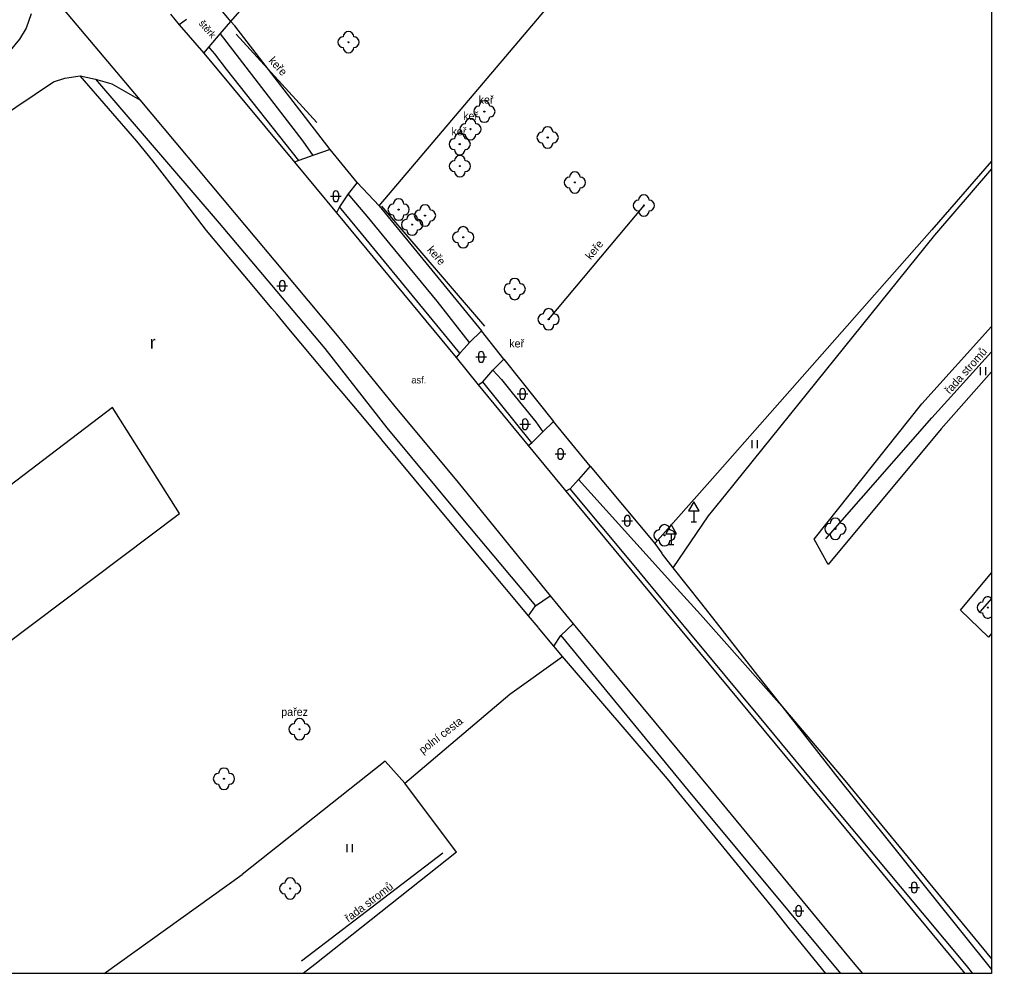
# Model space of a CAD drawing. Extents: x -594386 to -594050, y -1167541 to -1167175.
# Drawn here: x -594140.8 to -594049.8, y -1167540.8 to -1167451.4 of the extents above; entities that cross this region are included whole.
import ezdxf

# ---------------------------------------------------------------- set-up
doc = ezdxf.new("R2010")
doc.units = 0
for name, color, linetype in [('Level 14', 7, 'Continuous'), ('Level 22', 7, 'Continuous'), ('Level 34', 7, 'Continuous'), ('Level 36', 7, 'Continuous'), ('Level 41', 7, 'Continuous'), ('Vrstva 10', 7, 'Continuous'), ('Vrstva 11', 7, 'Continuous'), ('Vrstva 40', 7, 'Continuous'), ('Vrstva 42', 7, 'Continuous'), ('Vrstva 63', 7, 'Continuous'), ('Vrstva 7', 7, 'Continuous'), ('Vrstva 8', 7, 'Continuous')]:
    doc.layers.add(name, color=color, linetype=linetype)

msp = doc.modelspace()

# ---------------------------------------------------------------- linework, layer by layer
at = {"layer": 'Level 14'}
for points in [[(-594122.02, -1167452.75), (-594114.26, -1167462.8), (-594113.33, -1167464.15)], [(-594098.65, -1167481.66), (-594101.68, -1167477.78), (-594105.64, -1167472.99), (-594108.24, -1167469.82), (-594110.01, -1167467.73)], [(-594096.46, -1167484.27), (-594095.64, -1167485.14), (-594094.64, -1167486.38), (-594092.43, -1167489.11), (-594091.79, -1167490.03)]]:
    msp.add_lwpolyline(points, dxfattribs=at)
at = {"layer": 'Level 22'}
for centre in [(-594109.99, -1167453.53), (-594097.26, -1167460.03), (-594098.56, -1167461.68), (-594091.33, -1167462.46), (-594099.57, -1167463.08), (-594099.55, -1167465.14), (-594088.78, -1167466.67), (-594105.29, -1167469.21), (-594082.32, -1167468.83), (-594102.82, -1167469.77), (-594104.03, -1167470.62), (-594099.24, -1167471.81), (-594094.42, -1167476.66), (-594091.24, -1167479.49), (-594064.38, -1167499.12), (-594080.38, -1167499.73), (-594050.1, -1167506.5), (-594114.58, -1167517.9), (-594121.65, -1167522.54), (-594115.45, -1167532.82)]:
    msp.add_circle(centre, 0.05, dxfattribs=at)
for centre, start, end in [((-594109.99, -1167453.03), 0, 180), ((-594110.49, -1167453.53), 90, 270), ((-594109.49, -1167453.53), 270, 90), ((-594109.99, -1167454.03), 180, 0), ((-594097.26, -1167459.53), 0, 180), ((-594097.76, -1167460.03), 90, 270), ((-594096.76, -1167460.03), 270, 90), ((-594098.56, -1167461.18), 0, 180), ((-594097.26, -1167460.53), 180, 0), ((-594099.06, -1167461.68), 90, 270), ((-594098.06, -1167461.68), 270, 90), ((-594091.83, -1167462.46), 90, 270), ((-594091.33, -1167461.96), 0, 180), ((-594090.83, -1167462.46), 270, 90), ((-594100.07, -1167463.08), 90, 270), ((-594099.57, -1167462.58), 0, 180), ((-594099.07, -1167463.08), 270, 90), ((-594098.56, -1167462.18), 180, 0), ((-594099.57, -1167463.58), 180, 0), ((-594091.33, -1167462.96), 180, 0), ((-594100.05, -1167465.14), 90, 270), ((-594099.55, -1167464.64), 0, 180), ((-594099.05, -1167465.14), 270, 90), ((-594099.55, -1167465.64), 180, 0), ((-594088.78, -1167466.17), 0, 180), ((-594089.28, -1167466.67), 90, 270), ((-594088.28, -1167466.67), 270, 90), ((-594088.78, -1167467.17), 180, 0), ((-594105.29, -1167468.71), 0, 180), ((-594082.82, -1167468.83), 90, 270), ((-594082.32, -1167468.33), 0, 180), ((-594081.82, -1167468.83), 270, 90), ((-594105.79, -1167469.21), 90, 270), ((-594104.79, -1167469.21), 270, 90), ((-594103.32, -1167469.77), 90, 270), ((-594102.82, -1167469.27), 0, 180), ((-594102.32, -1167469.77), 270, 90), ((-594082.32, -1167469.33), 180, 0), ((-594105.29, -1167469.71), 180, 0), ((-594104.53, -1167470.62), 90, 270), ((-594104.03, -1167470.12), 0, 180), ((-594103.53, -1167470.62), 270, 90), ((-594104.03, -1167471.12), 180, 0), ((-594102.82, -1167470.27), 180, 0), ((-594099.24, -1167471.31), 0, 180), ((-594099.74, -1167471.81), 90, 270), ((-594098.74, -1167471.81), 270, 90), ((-594099.24, -1167472.31), 180, 0), ((-594094.42, -1167476.16), 0, 180), ((-594094.92, -1167476.66), 90, 270), ((-594093.92, -1167476.66), 270, 90), ((-594094.42, -1167477.16), 180, 0), ((-594091.74, -1167479.49), 90, 270), ((-594091.24, -1167478.99), 0, 180), ((-594090.74, -1167479.49), 270, 90), ((-594091.24, -1167479.99), 180, 0), ((-594064.38, -1167498.62), 0, 180), ((-594080.88, -1167499.73), 90, 270), ((-594080.38, -1167499.23), 0, 180), ((-594079.88, -1167499.73), 270, 90), ((-594064.88, -1167499.12), 90, 270), ((-594063.88, -1167499.12), 270, 90), ((-594080.38, -1167500.23), 180, 0), ((-594064.38, -1167499.62), 180, 0), ((-594050.1, -1167506), 45.573, 180), ((-594050.6, -1167506.5), 90, 270), ((-594050.1, -1167507), 180, 314.427), ((-594115.08, -1167517.9), 90, 270), ((-594114.58, -1167517.4), 0, 180), ((-594114.08, -1167517.9), 270, 90), ((-594114.58, -1167518.4), 180, 0), ((-594122.15, -1167522.54), 90, 270), ((-594121.65, -1167522.04), 0, 180), ((-594121.15, -1167522.54), 270, 90), ((-594121.65, -1167523.04), 180, 0), ((-594115.45, -1167532.32), 0, 180), ((-594115.95, -1167532.82), 90, 270), ((-594114.95, -1167532.82), 270, 90), ((-594115.45, -1167533.32), 180, 0)]:
    msp.add_arc(centre, 0.5, start, end, dxfattribs=at)
at = {"layer": 'Level 34'}
for p, q in [((-594077.64, -1167497.452), (-594077.64, -1167498.47)), ((-594077.89, -1167498.47), (-594077.39, -1167498.47)), ((-594079.77, -1167499.582), (-594079.77, -1167500.6)), ((-594080.02, -1167500.6), (-594079.52, -1167500.6))]:
    msp.add_line(p, q, dxfattribs=at)
for points in [[(-594078.14, -1167497.452), (-594077.14, -1167497.452), (-594077.64, -1167496.586)], [(-594080.27, -1167499.582), (-594079.27, -1167499.582), (-594079.77, -1167498.716)]]:
    msp.add_lwpolyline(points, close=True, dxfattribs=at)
at = {"layer": 'Level 36'}
for p, q in [((-594111.676, -1167467.966), (-594110.676, -1167467.966)), ((-594111.426, -1167467.716), (-594111.426, -1167468.216)), ((-594110.926, -1167467.716), (-594110.926, -1167468.216)), ((-594116.686, -1167476.356), (-594115.686, -1167476.356)), ((-594116.436, -1167476.106), (-594116.436, -1167476.606)), ((-594115.936, -1167476.106), (-594115.936, -1167476.606)), ((-594097.806, -1167482.766), (-594097.806, -1167483.266)), ((-594097.306, -1167482.766), (-594097.306, -1167483.266)), ((-594098.056, -1167483.016), (-594097.056, -1167483.016)), ((-594050.784, -1167484.723), (-594050.784, -1167483.973)), ((-594050.284, -1167484.723), (-594050.284, -1167483.973)), ((-594094.186, -1167486.486), (-594093.186, -1167486.486)), ((-594093.936, -1167486.236), (-594093.936, -1167486.736)), ((-594093.436, -1167486.236), (-594093.436, -1167486.736)), ((-594093.946, -1167489.326), (-594092.946, -1167489.326)), ((-594093.696, -1167489.076), (-594093.696, -1167489.576)), ((-594093.196, -1167489.076), (-594093.196, -1167489.576)), ((-594072.164, -1167491.553), (-594072.164, -1167490.803)), ((-594071.664, -1167491.553), (-594071.664, -1167490.803)), ((-594090.386, -1167491.856), (-594090.386, -1167492.356)), ((-594089.886, -1167491.856), (-594089.886, -1167492.356)), ((-594090.636, -1167492.106), (-594089.636, -1167492.106)), ((-594084.376, -1167498.366), (-594083.376, -1167498.366)), ((-594084.126, -1167498.116), (-594084.126, -1167498.616)), ((-594083.626, -1167498.116), (-594083.626, -1167498.616)), ((-594110.104, -1167529.423), (-594110.104, -1167528.673)), ((-594109.604, -1167529.423), (-594109.604, -1167528.673)), ((-594057.496, -1167532.726), (-594056.496, -1167532.726)), ((-594057.246, -1167532.476), (-594057.246, -1167532.976)), ((-594056.746, -1167532.476), (-594056.746, -1167532.976)), ((-594068.076, -1167534.676), (-594068.076, -1167535.176)), ((-594067.576, -1167534.676), (-594067.576, -1167535.176)), ((-594068.326, -1167534.926), (-594067.326, -1167534.926))]:
    msp.add_line(p, q, dxfattribs=at)
for centre, start, end in [((-594111.176, -1167467.716), 0, 180), ((-594111.176, -1167468.216), 180, 0), ((-594116.186, -1167476.106), 0, 180), ((-594116.186, -1167476.606), 180, 0), ((-594097.556, -1167482.766), 0, 180), ((-594097.556, -1167483.266), 180, 0), ((-594093.686, -1167486.236), 0, 180), ((-594093.686, -1167486.736), 180, 0), ((-594093.446, -1167489.076), 0, 180), ((-594093.446, -1167489.576), 180, 0), ((-594090.136, -1167491.856), 0, 180), ((-594090.136, -1167492.356), 180, 0), ((-594083.876, -1167498.116), 0, 180), ((-594083.876, -1167498.616), 180, 0), ((-594056.996, -1167532.476), 0, 180), ((-594056.996, -1167532.976), 180, 0), ((-594067.826, -1167534.676), 0, 180), ((-594067.826, -1167535.176), 180, 0)]:
    msp.add_arc(centre, 0.25, start, end, dxfattribs=at)
at = {"layer": 'Vrstva 10'}
for points in [[(-594140.14, -1167446.31), (-594129.52, -1167458.94)], [(-594139.7, -1167450.87), (-594140.18, -1167452.21), (-594140.81, -1167453.25), (-594141.67, -1167454.31), (-594142.79, -1167455.28), (-594143.9, -1167456.06)], [(-594126.67, -1167450.89), (-594125.84, -1167451.9)], [(-594125.84, -1167451.9), (-594123.54, -1167454.55)], [(-594123.54, -1167454.55), (-594115.06, -1167464.78)], [(-594142.9, -1167460.77), (-594137.62, -1167457.25), (-594136.57, -1167456.9), (-594135.11, -1167456.68)], [(-594135.11, -1167456.68), (-594133.67, -1167456.99)], [(-594133.67, -1167456.99), (-594132.15, -1167457.42), (-594129.52, -1167458.94)], [(-594129.52, -1167458.94), (-594120.69, -1167469.47), (-594115.06, -1167476.23)], [(-594115.06, -1167464.78), (-594111.12, -1167469.53)], [(-594111.12, -1167469.53), (-594099.9, -1167483.08)], [(-594115.06, -1167476.23), (-594111.04, -1167481.01), (-594105.76, -1167487.49)], [(-594099.9, -1167483.08), (-594097.84, -1167485.63)], [(-594097.84, -1167485.63), (-594093.16, -1167491.33)], [(-594105.76, -1167487.49), (-594099.7, -1167494.77), (-594091.09, -1167505.4)], [(-594093.16, -1167491.33), (-594089.63, -1167495.58)], [(-594089.63, -1167495.58), (-594065.5, -1167524.72), (-594052.244, -1167540.79)], [(-594091.09, -1167505.4), (-594088.93, -1167508.03)], [(-594088.93, -1167508.03), (-594076.06, -1167523.59), (-594062.72, -1167539.74), (-594061.849, -1167540.79)]]:
    msp.add_lwpolyline(points, dxfattribs=at)
at = {"layer": 'Vrstva 11'}
for p, q in [((-594049.75, -1167465.402), (-594055.1, -1167471.61)), ((-594049.75, -1167508.942), (-594050.03, -1167509.27)), ((-594132.872, -1167540.79), (-594119.96, -1167531.52))]:
    msp.add_line(p, q, dxfattribs=at)
for points in [[(-594121, -1167451.58), (-594079.89, -1167404.5), (-594071.72, -1167395.67)], [(-594125.15, -1167451.39), (-594125.84, -1167451.9)], [(-594122.02, -1167452.75), (-594121, -1167451.58)], [(-594123.05, -1167453.97), (-594122.02, -1167452.75)], [(-594123.54, -1167454.55), (-594123.05, -1167453.97)], [(-594114.63, -1167464.6), (-594121.41, -1167456.05), (-594122.52, -1167454.61), (-594122.93, -1167454.11), (-594123.05, -1167453.97)], [(-594117.16, -1167478.48), (-594118.85, -1167476.46), (-594121.51, -1167473.3), (-594121.83, -1167472.92), (-594123.29, -1167471.16), (-594125.23, -1167468.64), (-594125.61, -1167468.14), (-594128.33, -1167464.65), (-594129.81, -1167462.79), (-594135.11, -1167456.68)], [(-594133.67, -1167456.99), (-594122.09, -1167470.48), (-594117.2, -1167476.29)], [(-594111.7, -1167463.59), (-594113.33, -1167464.15)], [(-594114.63, -1167464.6), (-594115.06, -1167464.78)], [(-594113.33, -1167464.15), (-594114.63, -1167464.6)], [(-594109.16, -1167466.66), (-594110.01, -1167467.73)], [(-594110.01, -1167467.73), (-594110.82, -1167468.94)], [(-594110.82, -1167468.94), (-594111.12, -1167469.53)], [(-594099.55, -1167482.68), (-594108.78, -1167471.45), (-594110.82, -1167468.94)], [(-594055.1, -1167471.61), (-594074.667, -1167495.894)], [(-594117.2, -1167476.29), (-594112.21, -1167482.22), (-594106.4, -1167489.65)], [(-594106.87, -1167490.77), (-594106.94, -1167490.69), (-594109, -1167488.22), (-594110.49, -1167486.45), (-594111.07, -1167485.75), (-594115.56, -1167480.39), (-594116.71, -1167479.01), (-594117.16, -1167478.48)], [(-594049.75, -1167484.427), (-594054.46, -1167489.75), (-594065.04, -1167502.45), (-594066.37, -1167500.1), (-594056.27, -1167487.42), (-594049.75, -1167480.154)], [(-594097.52, -1167480.56), (-594098.65, -1167481.66)], [(-594098.65, -1167481.66), (-594099.15, -1167482.23), (-594099.55, -1167482.68)], [(-594099.55, -1167482.68), (-594099.9, -1167483.08)], [(-594096.46, -1167484.27), (-594095.45, -1167483.24)], [(-594097.41, -1167485.36), (-594096.46, -1167484.27)], [(-594097.84, -1167485.63), (-594097.41, -1167485.36)], [(-594092.8, -1167491.05), (-594097.41, -1167485.36)], [(-594183.067, -1167540.79), (-594125.813, -1167497.688), (-594132.097, -1167487.766), (-594201.7, -1167540.79)], [(-594091.79, -1167490.03), (-594090.78, -1167489.07)], [(-594106.4, -1167489.65), (-594099.47, -1167498.01), (-594092.48, -1167506.35)], [(-594092.8, -1167491.05), (-594091.79, -1167490.03)], [(-594093.12, -1167507.26), (-594097.39, -1167502.16), (-594100.73, -1167498.16), (-594106.87, -1167490.77)], [(-594093.16, -1167491.33), (-594092.8, -1167491.05)], [(-594087.34, -1167493.24), (-594088.45, -1167494.5)], [(-594088.45, -1167494.5), (-594089.23, -1167495.39)], [(-594088.45, -1167494.5), (-594079.51, -1167504.39)], [(-594089.23, -1167495.39), (-594089.63, -1167495.58)], [(-594051.49, -1167540.79), (-594052.1, -1167540.04), (-594064.45, -1167525.24), (-594071.5, -1167516.73), (-594078.09, -1167508.81), (-594083.22, -1167502.57), (-594089.23, -1167495.39)], [(-594074.667, -1167495.894), (-594076.3, -1167497.92)], [(-594076.3, -1167497.92), (-594079.59, -1167502.77)], [(-594081.29, -1167500.51), (-594080.65, -1167501.41), (-594080.59, -1167501.49), (-594079.59, -1167502.77)], [(-594079.59, -1167502.77), (-594076.93, -1167506.16), (-594074.99, -1167508.63), (-594071.68, -1167512.85), (-594069.41, -1167515.74)], [(-594050.03, -1167509.27), (-594052.67, -1167506.74), (-594049.75, -1167503.237)], [(-594079.51, -1167504.39), (-594077.02, -1167507.16), (-594069.41, -1167515.74)], [(-594092.48, -1167506.35), (-594091.09, -1167505.4)], [(-594093.12, -1167507.26), (-594092.48, -1167506.35)], [(-594092.18, -1167508.4), (-594092.23, -1167508.33), (-594093.12, -1167507.26)], [(-594090.76, -1167510.11), (-594092.18, -1167508.4)], [(-594090.11, -1167509.11), (-594088.93, -1167508.03)], [(-594090.76, -1167510.11), (-594090.11, -1167509.11)], [(-594090.11, -1167509.11), (-594078.16, -1167523.65), (-594063.893, -1167540.79)], [(-594089.931, -1167511.078), (-594090.76, -1167510.11)], [(-594104.72, -1167522.96), (-594094.86, -1167514.62), (-594089.931, -1167511.078)], [(-594065.27, -1167540.79), (-594068.67, -1167536.59), (-594070.09, -1167534.82), (-594074.81, -1167529.04), (-594079.32, -1167523.5), (-594079.83, -1167522.88), (-594080.1, -1167522.55), (-594089.931, -1167511.078)], [(-594069.41, -1167515.74), (-594063.48, -1167522.69), (-594049.75, -1167539.411)], [(-594069.41, -1167515.74), (-594065.37, -1167520.89), (-594064.02, -1167522.61), (-594059.56, -1167528.17), (-594055.43, -1167533.33), (-594049.75, -1167540.418)], [(-594106.56, -1167520.88), (-594119.96, -1167531.52)], [(-594106.56, -1167520.88), (-594104.72, -1167522.96)], [(-594099.86, -1167529.43), (-594104.72, -1167522.96)], [(-594099.86, -1167529.43), (-594113.15, -1167539.94), (-594114.244, -1167540.79)]]:
    msp.add_lwpolyline(points, dxfattribs=at)
at = {"layer": 'Vrstva 63'}
msp.add_lwpolyline([(-594386.36, -1167175.43), (-594049.75, -1167175.43), (-594049.75, -1167540.79), (-594386.36, -1167540.79)], close=True, dxfattribs=at)
at = {"layer": 'Vrstva 7'}
msp.add_line((-594049.75, -1167505.643), (-594050.82, -1167506.86), dxfattribs=at)
for points in [[(-594107.12, -1167468.87), (-594074.13, -1167429.94), (-594061.69, -1167415.02), (-594053.34, -1167405.27)], [(-594111.7, -1167463.59), (-594120.64, -1167452.01)], [(-594112.96, -1167461.04), (-594120.51, -1167452.77)], [(-594049.75, -1167464.666), (-594055.36, -1167471.12), (-594075.899, -1167494.399)], [(-594109.16, -1167466.66), (-594107.12, -1167468.87)], [(-594107.12, -1167468.87), (-594097.52, -1167480.56)], [(-594097.22, -1167480.13), (-594106.86, -1167468.9)], [(-594082.32, -1167468.83), (-594091.24, -1167479.49)], [(-594065.28, -1167500.05), (-594055.33, -1167488.72), (-594049.75, -1167482.539)], [(-594095.45, -1167483.24), (-594090.78, -1167489.07)], [(-594087.34, -1167493.24), (-594081.29, -1167500.51)], [(-594075.899, -1167494.399), (-594081.29, -1167500.51)], [(-594114.38, -1167539.61), (-594101.14, -1167529.48)]]:
    msp.add_lwpolyline(points, dxfattribs=at)
at = {"layer": 'Vrstva 8'}
for points in [[(-594121, -1167451.58), (-594122.67, -1167449.58)], [(-594120.64, -1167452.01), (-594121, -1167451.58)], [(-594109.16, -1167466.66), (-594111.7, -1167463.59)], [(-594095.45, -1167483.24), (-594097.52, -1167480.56)], [(-594087.34, -1167493.24), (-594090.78, -1167489.07)]]:
    msp.add_lwpolyline(points, dxfattribs=at)

# ---------------------------------------------------------------- texts
at = {"layer": 'Level 36'}
msp.add_text('r', height=1.2, dxfattribs=at).set_placement((-594128.593, -1167482.257))
at = {"layer": 'Level 41'}
for s, rotation, p in [('keře', 312.39415, (-594117.52, -1167455.31)), ('keře', 310.64328, (-594102.67, -1167473.02)), ('keře', 51.1939, (-594087.29, -1167473.97)), ('řada stromů', 48.17373, (-594053.67, -1167486.55)), ('řada stromů', 37.04605, (-594109.99, -1167536))]:
    msp.add_text(s, height=0.75, rotation=rotation, dxfattribs=at).set_placement(p)
for s, p in [('keř', (-594097.8, -1167459.29)), ('keř', (-594099.25, -1167460.81)), ('keř', (-594100.34, -1167462.26)), ('keř', (-594094.93, -1167482.13)), ('pařez', (-594116.29, -1167516.65))]:
    msp.add_text(s, height=0.75, dxfattribs=at).set_placement(p)
at = {"layer": 'Vrstva 40'}
msp.add_text('štěrk', height=0.65, rotation=311, dxfattribs=at).set_placement((-594124.06, -1167451.8))
msp.add_text('asf.', height=0.65, dxfattribs=at).set_placement((-594104.1, -1167485.5))
at = {"layer": 'Vrstva 42'}
msp.add_text('polní cesta', height=0.75, rotation=37.83799, dxfattribs=at).set_placement((-594103.03, -1167520.25))

doc.saveas('drawing.dxf')
